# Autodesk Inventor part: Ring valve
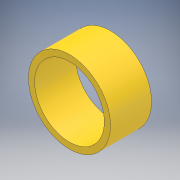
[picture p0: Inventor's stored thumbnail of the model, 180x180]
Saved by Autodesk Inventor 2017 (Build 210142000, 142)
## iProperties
Created: 2020-04
Part Number: Ring valve
Material: Generic
Document SubType Name: Modeling
Designer: user
Density: 1 g/cm^3
Appearance: Default
Author: user
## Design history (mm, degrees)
sketch "Sketch1"
  geometry: C1 r 10 at (0, 0); C2 r 8.5 at (0, 0); 1 further point
  constraints: 2 centre point, 1 coincident
  dimensions: "d0" = 20 diameter of C1; "d1" = 1.5 radial gap between concentric circles of C1 C2
extrude "Extrusion1" new body sketch "Sketch1" distance "d2" = 10; taper "d3" = 0 deg
body "Solid1"
